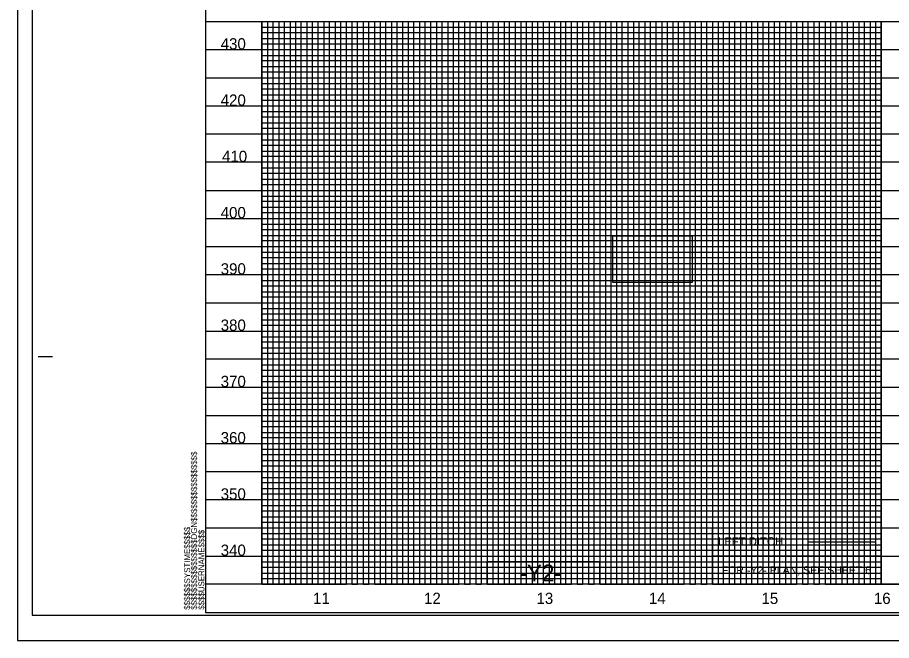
# Model space of a CAD drawing. Extents: x 1629737 to 1631945, y 1172886 to 1173986.
# Drawn here: x 1629737 to 1630513, y 1172886 to 1173440 of the extents above; entities that cross this region are included whole.
import ezdxf

# ---------------------------------------------------------------- set-up
doc = ezdxf.new("R2010")
doc.units = 0
for name, color, linetype in [('Exist Vertical Profile Horizontal Axis Label Major', 7, 'Continuous'), ('Exist Vertical Profile Vertical Axis Label', 7, 'Continuous'), ('Prop Grid Mask', 7, 'Continuous'), ('Prop PFL Ditch Label CELL', 7, 'Continuous'), ('Sheet Data Field CELL', 7, 'Continuous'), ('Sheet Layout Profile Border Port 2', 7, 'Continuous'), ('Sheet Plan CELL', 7, 'Continuous'), ('Sheet Plot Border Inside CELL', 7, 'Continuous'), ('Sheet Plot Border Outside CELL', 7, 'Continuous'), ('Sheet Profile CELL', 7, 'Continuous'), ('Sheet Profile Grid Major CELL', 7, 'Continuous'), ('Sheet Profile Grid Middle CELL', 7, 'Continuous'), ('Sheet Profile Grid Minor CELL', 7, 'Continuous')]:
    doc.layers.add(name, color=color, linetype=linetype)

msp = doc.modelspace()

# ---------------------------------------------------------------- linework, layer by layer
at = {"layer": 'Prop Grid Mask'}
for points in [[(1630265.86, 1173245.63), (1630336.37, 1173245.63), (1630336.37, 1173203.99), (1630265.86, 1173203.99)], [(1630354.31, 1172985.94), (1630504.31, 1172985.94), (1630504.31, 1172960.94), (1630354.31, 1172960.94)], [(1630154.31, 1172955.94), (1630254.31, 1172955.94), (1630254.31, 1172935.94), (1630154.31, 1172935.94)], [(1630354.31, 1172960.94), (1630504.31, 1172960.94), (1630504.31, 1172935.94), (1630354.31, 1172935.94)]]:
    msp.add_lwpolyline(points, close=True, dxfattribs=at)
at = {"layer": 'Prop PFL Ditch Label CELL'}
msp.add_line((1630439.86, 1172973.64), (1630499.86, 1172973.64), dxfattribs=at)
at = {"layer": 'Sheet Data Field CELL'}
msp.add_lwpolyline([(1630504.31, 1172935.94), (1630354.31, 1172935.94), (1630354.31, 1172960.94), (1630504.31, 1172960.94)], dxfattribs=at)
at = {"layer": 'Sheet Layout Profile Border Port 2'}
msp.add_lwpolyline([(1629954.31, 1173435.94), (1630504.31, 1173435.94), (1630504.31, 1172935.94), (1630254.31, 1172935.94), (1630254.31, 1172955.94), (1630154.31, 1172955.94), (1630154.31, 1172935.94), (1629954.31, 1172935.94)], close=True, dxfattribs=at)
at = {"layer": 'Sheet Plot Border Inside CELL'}
msp.add_lwpolyline([(1629750.31, 1172908.39), (1631416.81, 1172908.39), (1631416.81, 1173963.49), (1629750.31, 1173963.49)], close=True, dxfattribs=at)
at = {"layer": 'Sheet Plot Border Outside CELL'}
msp.add_lwpolyline([(1629737.31, 1172885.94), (1631421.31, 1172885.94), (1631421.31, 1173985.94), (1629737.31, 1173985.94)], close=True, dxfattribs=at)
at = {"layer": 'Sheet Profile CELL'}
for p, q in [((1629904.31, 1173435.94), (1631404.31, 1173435.94)), ((1629755.81, 1173138.44), (1629768.31, 1173138.44)), ((1631404.31, 1172935.94), (1629904.31, 1172935.94)), ((1629904.31, 1172910.94), (1631404.31, 1172910.94)), ((1629904.31, 1172910.94), (1629904.31, 1172910.94)), ((1629904.31, 1172910.94), (1629904.31, 1172910.94)), ((1629904.31, 1172910.94), (1629904.31, 1172910.94)), ((1629904.31, 1172910.94), (1629904.31, 1172910.94)), ((1629904.31, 1172910.94), (1629904.31, 1172910.94)), ((1629904.31, 1172910.94), (1629904.31, 1172910.94)), ((1629904.31, 1172910.94), (1629904.31, 1172910.94))]:
    msp.add_line(p, q, dxfattribs=at)
msp.add_lwpolyline([(1631404.31, 1173960.94), (1629904.31, 1173960.94), (1629904.31, 1172910.94), (1631404.31, 1172910.94)], close=True, dxfattribs=at)
msp.add_lwpolyline([(1629941.81, 1172910.94), (1629941.81, 1172910.94)], dxfattribs=at)
at = {"layer": 'Sheet Profile Grid Major CELL'}
for p, q in [((1629954.31, 1173435.94), (1629954.31, 1172935.94)), ((1630004.31, 1172935.94), (1630004.31, 1173435.94)), ((1630004.31, 1173435.94), (1630054.31, 1173435.94)), ((1630054.31, 1173435.94), (1630054.31, 1172935.94)), ((1630104.31, 1172935.94), (1630104.31, 1173435.94)), ((1630104.31, 1173435.94), (1630154.31, 1173435.94)), ((1630154.31, 1173435.94), (1630154.31, 1172935.94)), ((1630204.31, 1172935.94), (1630204.31, 1173435.94)), ((1630204.31, 1173435.94), (1630254.31, 1173435.94)), ((1630254.31, 1173435.94), (1630254.31, 1172935.94)), ((1630304.31, 1172935.94), (1630304.31, 1173435.94)), ((1630304.31, 1173435.94), (1630354.31, 1173435.94)), ((1630354.31, 1173435.94), (1630354.31, 1172935.94)), ((1630404.31, 1173435.94), (1630454.31, 1173435.94)), ((1630404.31, 1172935.94), (1630404.31, 1173435.94)), ((1630404.31, 1173435.94), (1630454.31, 1173435.94)), ((1630454.31, 1173435.94), (1630454.31, 1172935.94)), ((1630504.31, 1173435.94), (1630554.31, 1173435.94)), ((1630504.31, 1172935.94), (1630504.31, 1173435.94)), ((1630504.31, 1173435.94), (1630554.31, 1173435.94)), ((1629904.31, 1172935.94), (1629904.31, 1172935.94)), ((1629954.31, 1172935.94), (1630004.31, 1172935.94)), ((1630054.31, 1172935.94), (1630104.31, 1172935.94)), ((1630154.31, 1172935.94), (1630204.31, 1172935.94)), ((1630254.31, 1172935.94), (1630304.31, 1172935.94)), ((1630354.31, 1172935.94), (1630404.31, 1172935.94)), ((1630454.31, 1172935.94), (1630504.31, 1172935.94))]:
    msp.add_line(p, q, dxfattribs=at)
for points in [[(1631404.31, 1173410.94), (1629904.31, 1173410.94)], [(1631404.31, 1173360.94), (1629904.31, 1173360.94)], [(1631404.31, 1173310.94), (1629904.31, 1173310.94), (1629904.31, 1173260.94), (1631404.31, 1173260.94)], [(1631404.31, 1173210.94), (1629904.31, 1173210.94), (1629904.31, 1173160.94), (1631404.31, 1173160.94)], [(1631404.31, 1173110.94), (1629904.31, 1173110.94), (1629904.31, 1173060.94), (1631404.31, 1173060.94)], [(1631404.31, 1173010.94), (1629904.31, 1173010.94), (1629904.31, 1173010.94), (1629904.31, 1172960.94), (1631404.31, 1172960.94)], [(1631404.31, 1172935.94), (1629904.31, 1172935.94)]]:
    msp.add_lwpolyline(points, dxfattribs=at)
at = {"layer": 'Sheet Profile Grid Middle CELL'}
for p, q in [((1629929.31, 1173435.94), (1629979.31, 1173435.94)), ((1629979.31, 1173435.94), (1629979.31, 1172935.94)), ((1630029.31, 1172935.94), (1630029.31, 1173435.94)), ((1630029.31, 1173435.94), (1630079.31, 1173435.94)), ((1630079.31, 1173435.94), (1630079.31, 1172935.94)), ((1630129.31, 1172935.94), (1630129.31, 1173435.94)), ((1630129.31, 1173435.94), (1630179.31, 1173435.94)), ((1630179.31, 1173435.94), (1630179.31, 1172935.94)), ((1630229.31, 1172935.94), (1630229.31, 1173435.94)), ((1630229.31, 1173435.94), (1630279.31, 1173435.94)), ((1630279.31, 1173435.94), (1630279.31, 1172935.94)), ((1630329.31, 1172935.94), (1630329.31, 1173435.94)), ((1630329.31, 1173435.94), (1630379.31, 1173435.94)), ((1630379.31, 1173435.94), (1630379.31, 1172935.94)), ((1630429.31, 1172935.94), (1630429.31, 1173435.94)), ((1630429.31, 1173435.94), (1630479.31, 1173435.94)), ((1630479.31, 1173435.94), (1630479.31, 1172935.94)), ((1629979.31, 1172935.94), (1630029.31, 1172935.94)), ((1630079.31, 1172935.94), (1630129.31, 1172935.94)), ((1630179.31, 1172935.94), (1630229.31, 1172935.94)), ((1630279.31, 1172935.94), (1630329.31, 1172935.94)), ((1630379.31, 1172935.94), (1630429.31, 1172935.94)), ((1630479.31, 1172935.94), (1630529.31, 1172935.94))]:
    msp.add_line(p, q, dxfattribs=at)
for points in [[(1629904.31, 1173385.94), (1631404.31, 1173385.94)], [(1631404.31, 1173335.94), (1629904.31, 1173335.94), (1629904.31, 1173285.94), (1631404.31, 1173285.94)], [(1631404.31, 1173235.94), (1629904.31, 1173235.94), (1629904.31, 1173185.94), (1631404.31, 1173185.94)], [(1631404.31, 1173135.94), (1629904.31, 1173135.94), (1629904.31, 1173085.94), (1631404.31, 1173085.94)], [(1631404.31, 1173035.94), (1629904.31, 1173035.94), (1629904.31, 1172985.94), (1631404.31, 1172985.94)], [(1631404.31, 1172935.94), (1629904.31, 1172935.94)]]:
    msp.add_lwpolyline(points, dxfattribs=at)
at = {"layer": 'Sheet Profile Grid Minor CELL'}
for p, q in [((1629954.31, 1173430.94), (1630504.31, 1173430.94)), ((1630484.31, 1173435.94), (1630484.31, 1172935.94)), ((1630489.31, 1172935.94), (1630489.31, 1173435.94)), ((1630489.31, 1173435.94), (1630494.31, 1173435.94)), ((1630494.31, 1173435.94), (1630494.31, 1172935.94)), ((1630499.31, 1172935.94), (1630499.31, 1173435.94)), ((1630499.31, 1173435.94), (1630509.31, 1173435.94)), ((1630504.31, 1173425.94), (1629954.31, 1173425.94)), ((1629954.31, 1173420.94), (1630504.31, 1173420.94)), ((1630504.31, 1173415.94), (1629954.31, 1173415.94)), ((1629954.31, 1173405.94), (1630504.31, 1173405.94)), ((1630504.31, 1173400.94), (1629954.31, 1173400.94)), ((1629954.31, 1173395.94), (1630504.31, 1173395.94)), ((1630504.31, 1173390.94), (1629954.31, 1173390.94)), ((1629954.31, 1173380.94), (1630504.31, 1173380.94)), ((1630504.31, 1173375.94), (1629954.31, 1173375.94)), ((1629954.31, 1173370.94), (1630504.31, 1173370.94)), ((1630504.31, 1173365.94), (1629954.31, 1173365.94)), ((1629954.31, 1173355.94), (1630504.31, 1173355.94)), ((1630504.31, 1173350.94), (1629954.31, 1173350.94)), ((1629954.31, 1173345.94), (1630504.31, 1173345.94)), ((1630504.31, 1173340.94), (1629954.31, 1173340.94)), ((1629954.31, 1173330.94), (1630504.31, 1173330.94)), ((1630504.31, 1173325.94), (1629954.31, 1173325.94)), ((1629954.31, 1173320.94), (1630504.31, 1173320.94)), ((1630504.31, 1173315.94), (1629954.31, 1173315.94)), ((1629954.31, 1173305.94), (1630504.31, 1173305.94)), ((1630504.31, 1173300.94), (1629954.31, 1173300.94)), ((1629954.31, 1173295.94), (1630504.31, 1173295.94)), ((1630504.31, 1173290.94), (1629954.31, 1173290.94)), ((1629954.31, 1173280.94), (1630504.31, 1173280.94)), ((1630504.31, 1173275.94), (1629954.31, 1173275.94)), ((1629954.31, 1173270.94), (1630504.31, 1173270.94)), ((1630504.31, 1173265.94), (1629954.31, 1173265.94)), ((1629954.31, 1173255.94), (1630504.31, 1173255.94)), ((1630504.31, 1173250.94), (1629954.31, 1173250.94)), ((1629954.31, 1173245.94), (1630504.31, 1173245.94)), ((1630504.31, 1173241.03), (1629954.31, 1173241.09)), ((1629954.31, 1173230.94), (1630504.31, 1173230.94)), ((1630504.31, 1173225.94), (1629954.31, 1173225.94)), ((1629954.31, 1173220.94), (1630504.31, 1173220.94)), ((1630504.31, 1173215.94), (1629954.31, 1173215.94)), ((1629954.31, 1173205.94), (1630504.31, 1173205.94)), ((1630504.31, 1173200.94), (1629954.31, 1173200.94)), ((1629954.31, 1173195.94), (1630504.31, 1173195.94)), ((1630504.31, 1173190.94), (1629954.31, 1173190.94)), ((1629954.31, 1173180.94), (1630504.31, 1173180.94)), ((1630504.31, 1173175.94), (1629954.31, 1173175.94)), ((1629954.31, 1173170.94), (1630504.31, 1173170.94)), ((1630504.31, 1173165.94), (1629954.31, 1173165.94)), ((1629954.31, 1173155.94), (1630504.31, 1173155.94)), ((1630504.31, 1173150.94), (1629954.31, 1173150.94)), ((1629954.31, 1173145.94), (1630504.31, 1173145.94)), ((1630504.31, 1173140.94), (1629954.31, 1173140.94)), ((1629954.31, 1173130.94), (1630504.31, 1173130.94)), ((1630504.31, 1173125.94), (1629954.31, 1173125.94)), ((1629954.31, 1173120.94), (1630504.31, 1173120.94)), ((1630504.31, 1173115.94), (1629954.31, 1173115.94)), ((1629954.31, 1173105.94), (1630504.31, 1173105.94)), ((1630504.31, 1173100.94), (1629954.31, 1173100.94)), ((1629954.31, 1173095.94), (1630504.31, 1173095.94)), ((1630504.31, 1173090.94), (1629954.31, 1173090.94)), ((1629954.31, 1173080.94), (1630504.31, 1173080.94)), ((1630504.31, 1173075.94), (1629954.31, 1173075.94)), ((1629954.31, 1173070.94), (1630504.31, 1173070.94)), ((1630504.31, 1173065.94), (1629954.31, 1173065.94)), ((1629954.31, 1173055.94), (1630504.31, 1173055.94)), ((1630504.31, 1173050.94), (1629954.31, 1173050.94)), ((1629954.31, 1173045.94), (1630504.31, 1173045.94)), ((1630504.31, 1173040.94), (1629954.31, 1173040.94)), ((1629954.31, 1173030.94), (1630504.31, 1173030.94)), ((1630504.31, 1173025.94), (1629954.31, 1173025.94)), ((1629954.31, 1173020.94), (1630504.31, 1173020.94)), ((1630504.31, 1173015.94), (1629954.31, 1173015.94)), ((1629954.31, 1173005.94), (1630504.31, 1173005.94)), ((1630504.31, 1173000.94), (1629954.31, 1173000.94)), ((1629954.31, 1172995.94), (1630504.31, 1172995.94)), ((1630504.31, 1172990.94), (1629954.31, 1172990.94)), ((1629954.31, 1172980.94), (1630504.31, 1172980.94)), ((1630504.31, 1172975.94), (1629954.31, 1172975.94)), ((1629954.31, 1172970.94), (1630504.31, 1172970.94)), ((1630504.31, 1172965.94), (1629954.31, 1172965.94)), ((1629954.31, 1172955.94), (1630504.31, 1172955.94)), ((1630504.31, 1172950.94), (1629954.31, 1172950.94)), ((1629954.31, 1172945.94), (1630504.31, 1172945.94)), ((1629954.31, 1172940.94), (1630504.31, 1172940.94)), ((1630484.31, 1172935.94), (1630489.31, 1172935.94)), ((1630494.31, 1172935.94), (1630499.31, 1172935.94)), ((1630509.31, 1172935.94), (1630514.31, 1172935.94))]:
    msp.add_line(p, q, dxfattribs=at)
for points in [[(1629954.31, 1173435.94), (1629959.31, 1173435.94), (1629959.31, 1172935.94), (1629964.31, 1172935.94), (1629964.31, 1173435.94), (1629969.31, 1173435.94), (1629969.31, 1172935.94), (1629974.31, 1172935.94), (1629974.31, 1173435.94), (1629984.31, 1173435.94), (1629984.31, 1172935.94), (1629989.31, 1172935.94), (1629989.31, 1173435.94), (1629994.31, 1173435.94), (1629994.31, 1172935.94), (1629999.31, 1172935.94), (1630009.31, 1172935.94), (1630014.31, 1172935.94), (1630014.31, 1173435.94), (1630019.31, 1173435.94), (1630019.31, 1172935.94), (1630024.31, 1172935.94), (1630024.31, 1173435.94), (1630034.31, 1173435.94), (1630034.31, 1172935.94), (1630039.31, 1172935.94), (1630039.31, 1173435.94), (1630044.31, 1173435.94), (1630044.31, 1172935.94), (1630049.31, 1172935.94), (1630049.31, 1173435.94), (1630059.31, 1173435.94), (1630059.31, 1172935.94), (1630064.31, 1172935.94), (1630064.31, 1173435.94), (1630069.31, 1173435.94), (1630069.31, 1172935.94), (1630074.31, 1172935.94), (1630074.31, 1173435.94), (1630084.31, 1173435.94), (1630084.31, 1172935.94), (1630089.31, 1172935.94), (1630089.31, 1173435.94), (1630094.31, 1173435.94), (1630094.31, 1172935.94), (1630099.31, 1172935.94), (1630099.31, 1173435.94), (1630109.31, 1173435.94), (1630109.31, 1172935.94), (1630114.31, 1172935.94), (1630114.31, 1173435.94), (1630119.31, 1173435.94), (1630119.31, 1172935.94), (1630124.31, 1172935.94), (1630124.31, 1173435.94), (1630134.31, 1173435.94), (1630134.31, 1172935.94), (1630139.31, 1172935.94), (1630139.31, 1173435.94), (1630144.31, 1173435.94), (1630144.31, 1172935.94), (1630149.31, 1172935.94), (1630149.31, 1173435.94), (1630159.31, 1173435.94), (1630159.31, 1172935.94), (1630164.31, 1172935.94), (1630164.31, 1173435.94), (1630169.31, 1173435.94), (1630169.31, 1172935.94)], [(1629999.31, 1172935.94), (1629999.31, 1173435.94), (1630009.31, 1173435.94), (1630009.31, 1172935.94)], [(1630169.31, 1172935.94), (1630174.31, 1172935.94), (1630174.31, 1173435.94), (1630184.31, 1173435.94), (1630184.31, 1172935.94), (1630189.31, 1172935.94), (1630189.31, 1173435.94), (1630194.31, 1173435.94), (1630194.31, 1172935.94), (1630199.31, 1172935.94), (1630199.31, 1173435.94), (1630209.31, 1173435.94), (1630209.31, 1172935.94), (1630214.31, 1172935.94), (1630214.31, 1173435.94), (1630219.31, 1173435.94), (1630219.31, 1172935.94), (1630224.31, 1172935.94), (1630224.31, 1173435.94), (1630234.31, 1173435.94), (1630234.31, 1172935.94), (1630239.31, 1172935.94), (1630239.31, 1173435.94), (1630244.31, 1173435.94), (1630244.31, 1172935.94), (1630249.31, 1172935.94), (1630249.31, 1173435.94), (1630259.31, 1173435.94), (1630259.31, 1172935.94), (1630264.31, 1172935.94), (1630264.31, 1173435.94), (1630269.31, 1173435.94), (1630269.31, 1172935.94), (1630274.31, 1172935.94), (1630274.31, 1173435.94), (1630284.31, 1173435.94), (1630284.31, 1172935.94), (1630289.31, 1172935.94), (1630289.31, 1173435.94), (1630294.31, 1173435.94), (1630294.31, 1172935.94), (1630299.31, 1172935.94), (1630299.31, 1173435.94), (1630309.31, 1173435.94), (1630309.31, 1172935.94), (1630314.31, 1172935.94), (1630314.31, 1173435.94), (1630319.31, 1173435.94), (1630319.31, 1172935.94), (1630324.31, 1172935.94), (1630324.31, 1173435.94), (1630334.31, 1173435.94), (1630334.31, 1172935.94), (1630339.31, 1172935.94), (1630339.31, 1173435.94), (1630344.31, 1173435.94), (1630344.31, 1172935.94), (1630349.31, 1172935.94), (1630349.31, 1173435.94), (1630359.31, 1173435.94), (1630359.31, 1172935.94), (1630364.31, 1172935.94), (1630364.31, 1173435.94), (1630369.31, 1173435.94), (1630369.31, 1172935.94), (1630374.31, 1172935.94), (1630374.31, 1173435.94), (1630384.31, 1173435.94), (1630384.31, 1172935.94), (1630389.31, 1172935.94), (1630389.31, 1173435.94), (1630394.31, 1173435.94), (1630394.31, 1172935.94), (1630399.31, 1172935.94), (1630399.31, 1173435.94), (1630409.31, 1173435.94), (1630409.31, 1172935.94), (1630414.31, 1172935.94), (1630414.31, 1173435.94), (1630419.31, 1173435.94), (1630419.31, 1172935.94), (1630424.31, 1172935.94), (1630424.31, 1173435.94), (1630434.31, 1173435.94), (1630434.31, 1172935.94), (1630439.31, 1172935.94), (1630439.31, 1173435.94), (1630444.31, 1173435.94), (1630444.31, 1172935.94), (1630449.31, 1172935.94), (1630449.31, 1173435.94), (1630459.31, 1173435.94), (1630459.31, 1172935.94), (1630464.31, 1172935.94), (1630464.31, 1173435.94), (1630469.31, 1173435.94), (1630469.31, 1172935.94), (1630474.31, 1172935.94), (1630474.31, 1173435.94), (1630484.31, 1173435.94)]]:
    msp.add_lwpolyline(points, dxfattribs=at)

# ---------------------------------------------------------------- texts
at = {"layer": 'Exist Vertical Profile Horizontal Axis Label Major'}
for s, p in [('11', (1629999.74, 1172918.44)), ('12', (1630098.29, 1172918.44)), ('13', (1630198.12, 1172918.44)), ('14', (1630297.96, 1172918.44)), ('15', (1630397.89, 1172918.44)), ('16', (1630497.72, 1172918.44))]:
    msp.add_text(s, height=10, dxfattribs=at).set_placement(p)
at = {"layer": 'Exist Vertical Profile Vertical Axis Label'}
for s, p in [('430', (1629917.75, 1173411.19)), ('420', (1629917.75, 1173361.19)), ('410', (1629918.94, 1173311.19)), ('400', (1629917.75, 1173261.19)), ('390', (1629917.75, 1173211.19)), ('380', (1629917.75, 1173161.19)), ('370', (1629917.75, 1173111.19)), ('360', (1629917.75, 1173061.19)), ('350', (1629917.75, 1173011.19)), ('340', (1629917.75, 1172961.19))]:
    msp.add_text(s, height=10, dxfattribs=at).set_placement(p)
at = {"layer": 'Prop PFL Ditch Label CELL'}
msp.add_text('LEFT DITCH', height=7.485, dxfattribs=at).set_placement((1630359.31, 1172970.24))
at = {"layer": 'Sheet Data Field CELL'}
for s, height, p in [('-Y2-', 15, (1630182.88, 1172938.44)), ('FOR -Y2- PLAN, SEE SHEET 6', 7, (1630362.56, 1172944.94))]:
    msp.add_text(s, height=height, rotation=360, dxfattribs=at).set_placement(p)
at = {"layer": 'Sheet Plan CELL'}
for s, p in [('$$$$$$$$$$$$$$$$DGN$$$$$$$$$$$$$$$$', (1629896.68, 1172913.3)), ('$$$$$$SYSTIME$$$$$', (1629890.6, 1172913.28)), ('$$$$USERNAME$$$$', (1629903.23, 1172913.31))]:
    msp.add_text(s, height=5.25, rotation=90, dxfattribs=at).set_placement(p)

doc.saveas('drawing.dxf')
